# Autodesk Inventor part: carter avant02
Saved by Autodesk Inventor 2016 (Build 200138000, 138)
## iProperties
Created: 2013-10
Part Number: carter avant02
Material: Générique
Document SubType Name: Modeling
Designer: Bruno
Density: 1 g/cm^3
Appearance: Par défaut
Author: Bruno
Sending System: SolidWorks 2013
Last Author: christophe
Last Saved: 2014-02-15
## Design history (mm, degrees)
feature "Enlèv. mat.-Extru.12"
node "Solide1"
